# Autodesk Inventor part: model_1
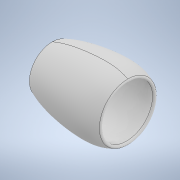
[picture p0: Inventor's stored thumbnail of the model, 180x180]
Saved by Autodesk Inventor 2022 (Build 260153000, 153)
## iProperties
Created: 2021-05
Part Number: model_1
Material: Všeobecné
Document SubType Name: Modeling
Designer: krejc
Density: 1 g/cm^3
Appearance: Výchozí
Mass: 215.964 g
Surface Area: 883.638 cm^2
Volume: 215.964 cm^3
Author: krejc
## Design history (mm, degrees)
sketch "profil"
  geometry: L1 (0, 0)-(-135, 0); L2 (0, 0)-(0, 60); L3 (-135, 0)-(-135, 56.25); L4 (-133.574, 39.757)-(-132.5, 37.5); L5 (-132.5, 37.5)-(-131.426, 35.243); L6 (-1.407, 49.748)-(-2.5, 47.5); L7 (-2.5, 47.5)-(-3.593, 45.252); L8 (-4.041, 42.477)-(-4.045, 42.469); A1 r 2.5 centre (-2.5, 47.5) between (-1.407, 49.748) and (-3.593, 45.252); A2 r 2.5 centre (-132.5, 37.5) between (-133.574, 39.757) and (-131.426, 35.243); A3 r 2.5 centre (-2.5, 47.5) between (-3.593, 45.252) and (-1.407, 49.748); A4 r 2.5 centre (-132.5, 37.5) between (-133.574, 39.757) and (-131.426, 35.243); 2 further points
  constraints: 16 end point, 8 point on circle, 4 centre point, 2 coincident, 2 point on line, 2 tangent, 2 vertical, 1 horizontal, 10 other
  dimensions: "d0" = 5 diameter of A1; "d1" = 5 diameter of A2; "d2" = 95 diameter of L6.end L1; "d4" = 75 diameter of L4.end L1; "d5" = 130 horizontal distance of L6.end L4.end; "d9" = 40 horizontal distance of L1.start point (-40, 57.5); "d11" = 115 diameter of point (-40, 57.5) L1; "d16" = 135 distance between parallel lines of L2 L3 (derived); "d65" = 5 distance of point (-40, 57.5) point (-40, 52.5)
revolve "Rotace1" sketch "profil" stored, may be unused: angle "d14" = 360 deg
feature "Rozdělit1"
node "Těleso1"
